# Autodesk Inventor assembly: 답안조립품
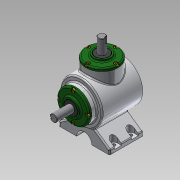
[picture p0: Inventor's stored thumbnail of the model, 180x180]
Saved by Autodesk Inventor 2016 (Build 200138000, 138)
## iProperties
Created: 2017-04
Part Number: 답안조립품
Material: 일반
Document SubType Name: Assembly
Designer: H
Author: H
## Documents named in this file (14)
- C:\Users\CAMTIC\Desktop\470407V1024\답안조립품.iam
- C:\Users\CAMTIC\Desktop\470407V1024\1-본체.ipt
- C:\Users\CAMTIC\Desktop\470407V1024\메인 베벨기어.ipt
- C:\Users\CAMTIC\Desktop\470407V1024\메인 축.ipt
- 메인 축.ipt
- C:\Users\CAMTIC\Desktop\470407V1024\베어링 6203.ipt
- C:\Users\CAMTIC\Desktop\470407V1024\볼트 M4.ipt
- C:\Users\CAMTIC\Desktop\470407V1024\서브 베벨기어.ipt
- C:\Users\CAMTIC\Desktop\470407V1024\서브 축.ipt
- 서브 축.ipt
- C:\Users\CAMTIC\Desktop\470407V1024\오일실 17 32 8.ipt
- C:\Users\CAMTIC\Desktop\470407V1024\커버.ipt
- C:\Users\CAMTIC\Desktop\470407V1024\키 4x4.ipt
- C:\Users\CAMTIC\Desktop\470407V1024\키 5x5.ipt
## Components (1 placed, 1 different names)
1. 1-본체:1
